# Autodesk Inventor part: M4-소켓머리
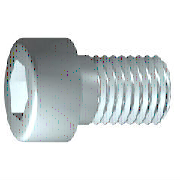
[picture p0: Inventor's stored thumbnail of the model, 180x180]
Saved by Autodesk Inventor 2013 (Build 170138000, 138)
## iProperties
IsCustomPart: 0
Company: 한국ATC센터
Created: 2014-08
Part Number: M4-소켓머리
Material: 강, 연강
Description: 6각머리 태핑 나사
Document SubType Name: Modeling
Standard: KS B 1003
Designer: KYOUNG IL JANG
Standards Organization: KS
Language: ko-KR
Size Designation: M 4 x 12
Categories: <MemberInstance><Categories><Category DisplayName="조임쇠" InternalName="e4da775c-781d-43d5-af7c-5136215cf5a6" Mnemonic="FSTN"><Category DisplayName="볼트" InternalN
Density: 1 g/cm^3
Checked By: KYOUNG IL JANG
Author: KYOUNG IL JANG
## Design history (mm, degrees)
sketch "스케치1"
  geometry: L1 (-1, 0)-(12, 0); L2 (12, 0)-(12, 2); L3 (12, 2)-(1.75, 2); L4 (1.75, 2)-(1.32, 2); L5 (1.32, 2)-(0, 2); L6 (0, 2)-(0, 3.5); L7 (0, 3.5)-(-4, 3.5); L8 (-4, 3.5)-(-4, 1.732); L9 (-4, 1.732)-(-2, 1.732); L10 (-2, 1.732)-(-1, 0); L11 (-7.2, 0)-(15.2, 0) reference; L12 (0, -0.7)-(0, 4.2) reference; L13 (1.75, 2)-(0, 2)
  constraints: 22 end point, 6 parallel, 2 collinear, 2 perpendicular, 1 horizontal, 1 point on line
  dimensions: "d1" = 10.25 distance from line of L3.end L2 (= GEL); "d2" = 0.42952 distance of L4.end L3.end (computed from GAL); "d3" = 4 distance between parallel lines of L8 L6 (= KOH); "d4" = 2 distance of L8.end L9.end (= INTI); "d5" = 60 deg angle of L10 L1; "d6" = 4 diameter of L3 L1 (= GD); "d7" = 4 diameter of L5 L1 (= BDM); "d8" = 3.4641 diameter of L9 L1 (= 1.1547 x SW); "d9" = 7 diameter of L7 L1 (= KOD); "d26" = 12 distance between parallel lines of L12 L2 (= NLG)
revolve "본체" sketch "스케치1" stored, may be unused: angle "d10" = 90 deg
sketch "스케치2"
  geometry: L1 (0, -4.9)-(0, 4.9) reference; L2 (-4.9, 0)-(4.9, 0) reference; L3 (1.732, 0)-(0.866, -1.5); L4 (0.866, -1.5)-(-0.866, -1.5); L5 (-0.866, -1.5)-(-1.732, 0); L6 (-1.732, 0)-(-0.866, 1.5); L7 (-0.866, 1.5)-(0.866, 1.5); L8 (0.866, 1.5)-(1.732, 0); 2 further points
  constraints: 12 end point, 1 coincident, 1 horizontal alignment, 1 point on line, 12 other
extrude "슬롯" join sketch "스케치2" stored distance "d11" = 10; taper "d12" = 0 deg
workplane "Work Plane1"
fillet "Fillet2" dims "d30" = 0.1 (= R)
body "Solid1"
fillet "모깎기1" dims "d17" = 0.4 (= RR)
feature "스레드" dims "d13" = 10.25 (= GEL), "d14" = 0
chamfer "모따기1" distance "d15" = 0.42941 (= -0.5 x SPD + 0.5 x GD); stored, may be unused: second distance "d16" = 0.42941 (= GUL), angle "d27" = 45 deg
other parameters: "GD" = 4 (= NND) [user parameter; used in 2 equation terms], "NLG" = 12 [user parameter; used in 1 equation term], "GEL" = 10.25 [user parameter; used in 2 equation terms], "KOD" = 7 [user parameter; used in 1 equation term], "KOH" = 4 [user parameter; used in 1 equation term], "INTI" = 2 [user parameter; used in 1 equation term], "GAL" = 0.42941 (= 0.61345 x PTC) [user parameter; used in 1 equation term], "GUL" = 0.42941 (= 0.61345 x PTC) [user parameter; used in 1 equation term], "BDM" = 4 (= NND) [user parameter; used in 1 equation term], "SW" = 3 [user parameter; used in 2 equation terms], "RR" = 0.4 [user parameter; used in 1 equation term], "SPD" = 3.14117 (= NND - 1.2269 x PTC) [user parameter; used in 1 equation term], "d19" = 0, "d28" = 0, "d29" = 0, "R" = 0.1 [user parameter; used in 1 equation term], "PHH" = 0.2 [user parameter], "GD1" = 3.14117 (= THREADDIA - 1.2269 x PTC) [user parameter], "THREADDIA" = 4 [user parameter; used in 1 equation term], "FAWI" = 45 deg [user parameter], "TPU" = 14.28571 (computed from PTC) [user parameter], "PTC" = 0.7 [user parameter; used in 5 equation terms], "NND" = 4 [user parameter; used in 3 equation terms], "TOA" = 30 deg [user parameter], "E0" = 3.465 (= 1.155 x SW) [user parameter]
